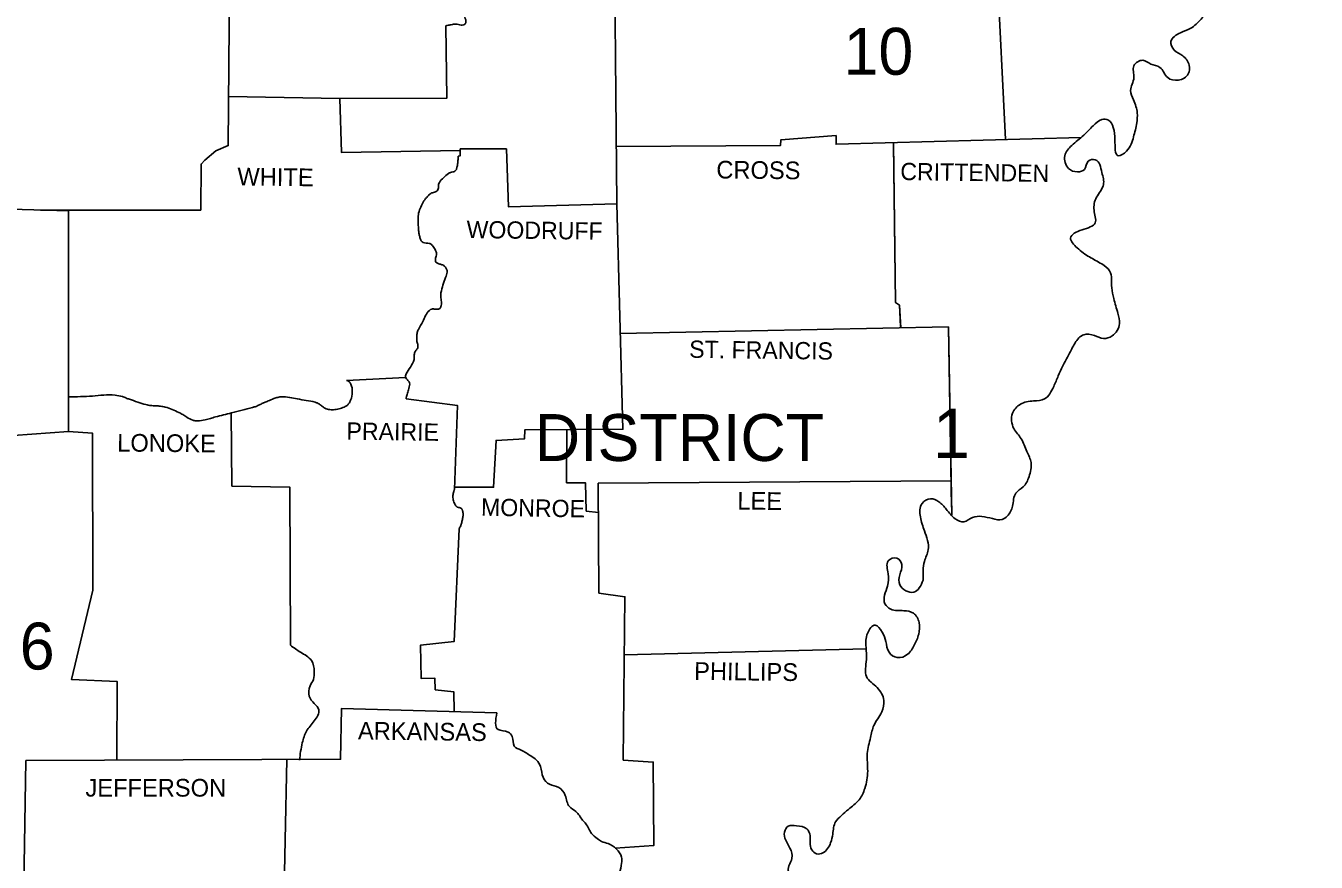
# Model space of a CAD drawing. Extents: x 164 to 3385, y 68 to 2119.
# Drawn here: x 2994.5 to 3298, y 1627.9 to 1824.7 of the extents above; entities that cross this region are included whole.
import ezdxf

# ---------------------------------------------------------------- set-up
doc = ezdxf.new("R2010")
doc.units = 0
doc.layers.add('Default', color=7, linetype='Continuous')

msp = doc.modelspace()

# ---------------------------------------------------------------- linework, layer by layer
at = {"layer": 'Default'}
msp.add_line((3096.73, 1795.77), (3107.55, 1795.77), dxfattribs=at)
for points in [[(3087.23, 1952.28), (3086.86, 1949.35), (3088.8, 1949.06), (3088.7, 1947.89), (3090.92, 1947.41), (3091.12, 1945.86), (3092.18, 1945.18), (3092.47, 1940.54), (3097.99, 1939.96), (3097.99, 1935.8), (3100.02, 1935.51), (3100.02, 1933.86), (3101.76, 1933.38), (3101.67, 1927.77), (3103.21, 1927.48), (3103.6, 1914.8), (3095.38, 1914.02), (3095.47, 1911.31), (3092.96, 1911.22), (3093.83, 1861.28), (3132.83, 1860.41), (3133.5, 1782.8), (3108.05, 1782.13), (3107.55, 1795.77)], [(2998.21, 1950.89), (2998.41, 1927.28), (2996.77, 1927.19), (2997.06, 1903.09), (2990.28, 1902.12), (2990.86, 1895.64), (2993.19, 1892.64), (2992.99, 1884.99), (2979.83, 1884.51), (2979.35, 1872.7), (2967.35, 1872.32), (2966.77, 1857.99), (2967.45, 1856.83), (2967.74, 1833.99), (2988.45, 1832.64), (2988.16, 1781.64), (3004.61, 1781.16), (3004.61, 1729.29), (2991.64, 1728.32), (2990.67, 1716.9), (2968.9, 1716.81)], [(3221.35, 1880.05), (3223.01, 1837.58), (3224.98, 1797.93)], [(2988.45, 1832.64), (3038.19, 1832.35), (3042.44, 1834.38), (3042.15, 1796.54), (3039.25, 1795.29), (3036.64, 1793.06), (3035.77, 1792.19), (3035.67, 1781.35), (2998.02, 1781.35)], [(3093.34, 1824.7), (3093.54, 1807.67), (3068.38, 1807.58), (3042.24, 1808.07)], [(3068.38, 1807.58), (3068.76, 1794.9), (3096.73, 1795.4)], [(3133.38, 1796.34), (3172.02, 1796.54), (3172.11, 1797.9), (3185.08, 1798.87), (3185.08, 1796.83), (3242.73, 1798.42)], [(3198.62, 1797.21), (3199.11, 1759.58), (3199.98, 1759), (3200.29, 1753.64)], [(3198.63, 1796.83), (3199.11, 1759.58), (3199.98, 1759), (3200.27, 1753.97)], [(3198.63, 1796.83), (3199.11, 1759.58), (3199.98, 1759), (3200.27, 1753.97)], [(3198.63, 1796.83), (3199.11, 1759.58), (3199.98, 1759), (3200.27, 1753.97)], [(3198.63, 1796.83), (3199.11, 1759.58), (3199.98, 1759), (3200.27, 1753.97)], [(3096.73, 1795.77), (3096.73, 1794.13), (3096.25, 1794.03)], [(3133.5, 1782.8), (3134.95, 1729.77), (3111.92, 1729.68), (3111.83, 1727.55), (3105.15, 1727.16), (3104.57, 1716.13), (3095.39, 1716.13)], [(3134.34, 1752.31), (3211.5, 1753.87)], [(3211.5, 1753.87), (3212.27, 1711.48)], [(3211.5, 1753.87), (3212.27, 1711.48)], [(3211.5, 1753.87), (3212.27, 1711.48)], [(3211.5, 1753.87), (3212.27, 1711.48)], [(3211.5, 1753.87), (3212.27, 1711.48)], [(3211.5, 1753.87), (3212.27, 1711.48)], [(3211.5, 1753.87), (3212.27, 1711.48)], [(3211.5, 1753.87), (3212.31, 1709.54)], [(3069.93, 1741.29), (3083.85, 1741.96)], [(3083.96, 1736.93), (3096.05, 1735.39), (3095.38, 1715.64)], [(3042.83, 1733.74), (3043.02, 1716.42), (3056.67, 1716.13), (3056.76, 1678.97)], [(3004.61, 1729.29), (3010.22, 1728.9), (3010.32, 1691.94), (3005.28, 1670.94), (3016.02, 1670.45), (3015.92, 1651.96)], [(3121.8, 1729.72), (3121.7, 1717.19), (3126.15, 1717.19), (3126.34, 1710.52), (3129.2, 1710.22)], [(3133.18, 1631.26), (3142.21, 1631.84), (3142.12, 1651.48), (3135.05, 1651.97), (3135.44, 1690.39), (3129.34, 1691.26), (3129.15, 1717.1), (3212.16, 1717.68)], [(3096.44, 1706.35), (3095.28, 1679.84), (3087.34, 1678.97), (3087.54, 1671.13), (3090.73, 1671.23), (3090.83, 1668.52), (3095.18, 1668.03), (3095.32, 1663.36)], [(3135.3, 1676.73), (3192.16, 1678.15)], [(3105.34, 1663.1), (3068.76, 1664.07), (3068.57, 1652.16), (2994.54, 1651.87)], [(2994.54, 1651.87), (2993.96, 1612.58), (2991.74, 1612.49), (2991.45, 1588.2)], [(3055.93, 1652.11), (3055.12, 1614.13), (3068.57, 1613.07)]]:
    msp.add_lwpolyline(points, dxfattribs=at)
for points in [[(3284.46, 1883.25), (3285.53, 1883.35), (3288.82, 1879.86), (3290.27, 1876.96), (3292.4, 1875.32), (3294.82, 1874.45), (3296.66, 1872.22), (3297.91, 1869.8), (3297.24, 1867.67), (3294.53, 1867.48), (3291.53, 1866.99), (3288.62, 1867.09), (3286.3, 1865.15), (3288.43, 1862.54), (3291.24, 1860.12), (3292.01, 1857.51), (3290.46, 1854.99), (3287.37, 1853.64), (3284.37, 1852.48), (3281.66, 1850.16), (3280.4, 1847.93), (3277.4, 1846.96), (3274.3, 1846.09), (3271.59, 1845.8), (3268.5, 1845.22), (3265.5, 1843.77), (3264.24, 1841.25), (3264.63, 1837.67), (3264.53, 1833.9), (3267.72, 1832.64), (3270.53, 1832.54), (3273.24, 1831.09), (3272.95, 1828.96), (3270.92, 1826.25), (3268.5, 1824.12), (3266.08, 1823.06), (3263.85, 1821.03), (3264.63, 1819), (3266.66, 1817.64), (3268.11, 1815.41), (3267.92, 1813.38), (3265.59, 1811.93), (3263.08, 1812.51), (3261.24, 1814.93), (3259.11, 1815.71), (3257.27, 1816.58), (3255.14, 1815.32), (3255.14, 1812.51), (3254.37, 1809.51), (3255.05, 1807.29), (3255.92, 1804.19), (3255.82, 1801.87), (3255.05, 1798.58), (3253.4, 1795.19), (3251.47, 1794.13), (3250.69, 1797.8), (3250.3, 1800.8), (3249.14, 1802.54), (3247.59, 1802.64), (3245.56, 1801.19), (3243.34, 1798.96), (3240.53, 1796.54), (3238.88, 1794.13), (3239.76, 1791.13), (3241.88, 1790.35), (3243.53, 1790.93), (3244.4, 1792.87), (3246.05, 1793.16), (3247.59, 1790.16)], [(3111.31, 1860.89), (3110.44, 1858.71), (3109.5, 1856.54), (3109.17, 1855.81), (3108.83, 1855.09), (3108.48, 1854.36), (3108.15, 1853.64), (3107.91, 1853.02), (3107.72, 1852.38), (3107.52, 1851.74), (3107.28, 1851.12), (3106.92, 1850.68), (3106.41, 1850.34), (3105.88, 1850.04), (3105.64, 1849.87), (3105.44, 1849.67), (3105.27, 1849.36), (3105.16, 1848.99), (3105.05, 1848.62), (3104.86, 1848.32), (3104.49, 1848.12), (3104.04, 1848.04), (3103.58, 1847.96), (3103.21, 1847.74), (3103.03, 1847.51), (3102.85, 1847.28), (3102.52, 1846.81), (3102.23, 1846.31), (3101.96, 1845.8), (3101.79, 1845.37), (3101.67, 1844.92), (3101.55, 1844.48), (3101.38, 1844.06), (3101.1, 1843.81), (3100.71, 1843.66), (3100.32, 1843.51), (3100.02, 1843.28), (3099.89, 1843.05), (3099.79, 1842.79), (3099.66, 1842.22), (3099.54, 1841.66), (3099.41, 1841.27), (3099.34, 1841.16), (3099.07, 1840.85), (3098.71, 1840.58), (3098.35, 1840.31), (3098.09, 1839.99), (3098.03, 1839.54), (3098.17, 1839.01), (3098.29, 1838.5), (3098.18, 1838.06), (3098.1, 1837.97), (3098.02, 1837.88), (3097.47, 1837.38), (3097.08, 1837.06), (3096.73, 1836.7), (3096.4, 1836.35), (3096.07, 1835.98), (3095.78, 1835.6), (3095.66, 1835.38), (3095.57, 1835.16), (3095.45, 1834.09), (3095.57, 1833.03), (3095.64, 1832.32), (3095.72, 1831.61), (3095.85, 1830.91), (3095.94, 1830.56), (3096.05, 1830.22), (3096.26, 1829.79), (3096.52, 1829.38), (3096.78, 1828.99), (3097.02, 1828.58), (3097.49, 1827.52), (3097.7, 1826.98), (3097.89, 1826.45), (3098, 1826.1), (3098.06, 1825.73), (3098.02, 1825.38), (3097.93, 1825.23), (3097.87, 1825.16), (3097.8, 1825.09), (3097.2, 1824.87), (3096.59, 1824.92), (3095.98, 1825.07), (3095.68, 1825.11), (3095.38, 1825.09), (3094.87, 1825.01), (3094.36, 1824.92), (3093.85, 1824.82), (3093.34, 1824.7)], [(3096.25, 1794.03), (3096.19, 1793.22), (3096.11, 1792.42), (3095.99, 1791.62), (3095.89, 1791.23), (3095.83, 1791.03), (3095.76, 1790.83), (3095.45, 1790.48), (3094.95, 1790.31), (3094.4, 1790.18), (3094.15, 1790.09), (3093.92, 1789.96), (3092.79, 1788.97), (3091.8, 1787.84), (3091.61, 1787.38), (3091.57, 1786.85), (3091.52, 1786.33), (3091.31, 1785.9), (3091.14, 1785.75), (3090.93, 1785.64), (3090.45, 1785.5), (3089.97, 1785.37), (3089.57, 1785.13), (3089.11, 1784.66), (3088.68, 1784.18), (3088.28, 1783.66), (3087.92, 1783.09), (3087.26, 1781.72), (3086.86, 1780.29), (3086.78, 1778.84), (3086.86, 1777.38), (3086.93, 1776.55), (3087.04, 1775.72), (3087.23, 1774.9), (3087.37, 1774.5), (3087.54, 1774.09), (3087.99, 1773.7), (3088.66, 1773.6), (3089.38, 1773.52), (3089.96, 1773.22), (3090.15, 1773), (3090.33, 1772.78), (3090.64, 1772.3), (3091.12, 1771.29), (3091.14, 1770.79), (3091, 1770.26), (3090.87, 1769.74), (3090.92, 1769.25), (3091.38, 1768.83), (3092.05, 1768.6), (3092.74, 1768.36), (3093.25, 1767.9), (3093.41, 1767.61), (3093.56, 1767.32), (3093.65, 1767.03), (3093.63, 1766.74), (3093.25, 1765.48), (3092.18, 1761.9), (3092.11, 1761.31), (3092.16, 1760.7), (3092.24, 1760.09), (3092.28, 1759.48), (3092.24, 1758.94), (3092.18, 1758.68), (3092.09, 1758.42), (3091.58, 1758.05), (3090.81, 1758.04), (3090.02, 1758.05), (3089.47, 1757.74), (3087.92, 1755.13), (3086.86, 1753.29), (3086.73, 1752.99), (3086.53, 1752.08), (3086.49, 1751.48), (3086.47, 1750.87), (3086.52, 1750.43), (3086.64, 1750), (3086.75, 1749.56), (3086.76, 1749.13), (3086.63, 1748.77), (3086.4, 1748.44), (3086.16, 1748.12), (3085.99, 1747.77), (3085.91, 1747.27), (3085.9, 1746.74), (3085.85, 1746.22), (3085.7, 1745.74), (3084.73, 1744), (3083.86, 1742.35), (3083.89, 1741.88), (3084.27, 1741.4), (3084.68, 1740.91), (3084.83, 1740.42), (3084.69, 1739.75), (3084.54, 1739.06), (3084.39, 1738.53), (3084.22, 1737.99), (3083.96, 1736.93)], [(3247.59, 1790.16), (3247.98, 1787.35), (3246.34, 1784.35), (3245.76, 1781.35), (3246.05, 1778.35), (3242.95, 1776.71), (3240.24, 1774.77), (3241.79, 1772.45), (3244.69, 1770.32), (3247.59, 1768.67), (3249.43, 1767.03), (3249.92, 1763.06), (3250.4, 1760.55), (3251.37, 1757.06), (3251.76, 1754.64), (3250.01, 1751.74), (3247.98, 1751.16), (3245.85, 1751.84), (3243.34, 1752.03), (3241.3, 1750.09), (3239.85, 1747.38), (3238.4, 1744.68), (3237.34, 1742.35), (3236.27, 1739.84), (3234.14, 1736.93), (3231.53, 1736.45), (3228.43, 1735.68), (3226.6, 1733.55), (3226.89, 1729.97), (3228.63, 1727.55), (3229.98, 1724.55), (3230.95, 1721.93), (3230.47, 1718.64), (3229.11, 1716.22), (3227.37, 1714.77), (3226.6, 1711.68), (3225.34, 1709.35), (3224.18, 1708.58), (3221.85, 1708.77), (3219.34, 1709.26), (3217.21, 1709.06), (3215.18, 1708), (3213.14, 1708.68), (3211.02, 1711), (3209.27, 1712.74), (3207.34, 1713.42), (3205.31, 1712.35), (3204.92, 1709.16), (3205.89, 1705.87), (3206.76, 1701.42), (3205.89, 1698.71), (3205.6, 1694.26)], [(3004.61, 1737.41), (3010.22, 1737.61), (3015.54, 1737.8), (3017.25, 1737.46), (3018.09, 1737.14), (3018.51, 1736.98), (3018.93, 1736.84), (3022.8, 1735.58), (3023.35, 1735.45), (3023.92, 1735.37), (3025.07, 1735.29), (3026.22, 1735.21), (3027.35, 1735), (3030.54, 1733.74), (3031.02, 1733.5), (3031.48, 1733.22), (3032.4, 1732.62), (3033.82, 1731.91), (3034.06, 1731.84), (3034.31, 1731.8), (3034.91, 1731.78), (3036.73, 1732.02), (3037.95, 1732.34), (3039.15, 1732.68), (3042.93, 1733.64), (3047.86, 1734.9), (3048.68, 1735.17), (3049.47, 1735.53), (3050.26, 1735.91), (3051.06, 1736.26), (3051.51, 1736.44), (3052.87, 1737), (3053.79, 1737.29), (3054.26, 1737.38), (3054.73, 1737.42), (3056.57, 1737.26), (3058.41, 1736.93), (3060.5, 1736.57), (3062.57, 1736.16), (3063.27, 1735.88), (3063.92, 1735.43), (3064.54, 1734.96), (3065.18, 1734.61), (3066.32, 1734.38), (3067.55, 1734.45), (3068.79, 1734.77), (3069.38, 1735.01), (3069.93, 1735.29), (3070.51, 1735.83), (3070.94, 1736.62), (3071.33, 1738.57), (3071.01, 1740.39), (3070.57, 1741), (3069.93, 1741.29)], [(3095.38, 1715.64), (3095.26, 1715.41), (3095.17, 1715.17), (3095.05, 1714.68), (3094.99, 1714.19), (3094.98, 1713.95), (3094.99, 1713.71), (3095.06, 1713.19), (3095.23, 1712.67), (3095.47, 1712.17), (3095.61, 1711.92), (3095.76, 1711.68), (3095.9, 1711.54), (3096.07, 1711.45), (3096.47, 1711.35), (3096.86, 1711.25), (3097.01, 1711.15), (3097.07, 1711.08), (3097.12, 1711), (3097.16, 1710.88), (3097.21, 1710.76), (3097.36, 1710.03), (3097.37, 1709.54), (3097.35, 1709.3), (3097.31, 1709.06), (3097.12, 1708.09), (3096.99, 1707.61), (3096.92, 1707.37), (3096.83, 1707.13), (3096.65, 1706.73), (3096.44, 1706.35)], [(3205.6, 1694.26), (3203.37, 1691.45), (3200.08, 1693.19), (3200.08, 1695.52), (3200.56, 1697.93), (3199.4, 1699.48), (3197.37, 1698.81), (3197.37, 1695.81), (3197.18, 1692.9), (3196.6, 1688.74), (3197.95, 1687.48), (3201.05, 1687.1), (3203.27, 1686.52), (3204.63, 1684.29), (3204.53, 1681.58), (3203.47, 1678.97), (3201.92, 1676.84), (3199.5, 1676.06), (3197.56, 1677.32), (3196.79, 1679.84), (3195.92, 1682.06), (3194.27, 1683.71), (3192.53, 1681.87), (3192.15, 1678.48), (3192.24, 1675.58), (3192.24, 1671.61), (3194.76, 1669), (3196.31, 1666), (3195.82, 1663.29), (3193.98, 1660.1), (3193.21, 1657.29), (3192.44, 1653.52), (3192.53, 1649.36), (3191.86, 1645.29), (3190.5, 1642.58), (3187.98, 1640.36), (3186.34, 1638.9), (3184.98, 1637.45), (3184.31, 1634.55), (3183.82, 1632.52), (3181.98, 1630.1), (3180.53, 1629.9), (3179.37, 1630.87), (3178.98, 1632.52), (3178.98, 1634.16), (3178.21, 1635.81), (3175.79, 1636.49), (3173.86, 1636.39), (3172.98, 1635.03), (3174.24, 1631.26), (3174.73, 1628.84), (3174.05, 1625.55), (3174.44, 1625.16), (3170.95, 1623.32), (3168.15, 1623.03), (3165.82, 1622.36), (3163.6, 1620.91), (3162.53, 1618.78), (3160.99, 1617.03), (3159.63, 1615.39), (3157.79, 1614.62), (3155.76, 1615), (3153.05, 1615.29), (3151.5, 1613.36), (3151.99, 1610.55), (3153.82, 1608.91), (3156.53, 1608.13), (3159.34, 1608.33), (3162.05, 1608.62), (3164.57, 1607.26), (3164.08, 1604.65), (3161.66, 1603.39), (3158.08, 1603), (3155.18, 1603.29), (3151.7, 1602.52), (3149.95, 1600.29), (3150.92, 1596.91), (3154.7, 1595.55), (3156.44, 1592.36), (3156.53, 1589.36), (3155.28, 1585.39), (3153.53, 1583.55), (3150.15, 1582.78), (3147.53, 1582.29), (3147.15, 1577.84), (3145.99, 1575.62), (3143.95, 1574.94), (3141.05, 1576.39), (3139.31, 1577.07), (3137.18, 1578.04), (3134.47, 1579.68), (3132.44, 1579.39), (3133.02, 1575.13), (3133.21, 1574.94), (3135.54, 1571.75), (3137.86, 1569.23), (3138.92, 1566.23)], [(3056.76, 1678.97), (3059.18, 1677.32), (3061.7, 1675.39), (3062.38, 1672.77), (3062.18, 1670.94), (3061.41, 1669.39), (3061.22, 1666.97), (3062.38, 1665.23), (3063.44, 1663.77), (3062.38, 1661.16), (3060.54, 1658.74), (3059.57, 1656.03), (3058.89, 1651.97)], [(3105.34, 1663.1), (3105.63, 1659.13), (3107.96, 1658.55), (3108.92, 1657.48), (3109.41, 1655.26), (3111.05, 1654.29), (3113.28, 1652.94), (3114.63, 1651.97), (3115.6, 1650.42), (3116.18, 1647.9), (3117.73, 1646.26), (3119.86, 1645.49), (3121.41, 1643.65), (3122.37, 1641.03), (3123.92, 1639.87), (3125.47, 1637.84), (3126.25, 1636.97), (3127.6, 1634.65), (3128.95, 1633.49), (3129.92, 1632.81), (3131.47, 1632.32), (3133.41, 1631.07), (3134.66, 1629.13), (3134.66, 1627.68), (3134.18, 1625.45), (3133.79, 1623.13), (3133.6, 1620.52), (3133.41, 1618.2), (3134.28, 1616.26), (3133.79, 1613.36), (3132.83, 1611.81), (3132.73, 1609.68), (3132.44, 1606.49), (3132.05, 1604.65), (3131.18, 1601.65), (3129.92, 1600.1)]]:
    msp.add_spline(points, degree=3, dxfattribs=at)

# ---------------------------------------------------------------- texts
for s, height, p in [('10', 11.032, (3186.85, 1813.19)), ('DISTRICT', 11.032, (3114.25, 1722.32)), ('1', 11.61, (3207.92, 1723)), ('DISTRICT 6', 11.032, (2921, 1673.26)), ('JEFFERSON', 4.161, (3008.57, 1643.36))]:
    msp.add_text(s, height=height, dxfattribs=at).set_placement(p)
for s, height, rotation, p in [('WHITE', 4.162, 359.3138, (3044.28, 1787.16)), ('CROSS', 4.161, 359.3839, (3156.92, 1788.8)), ('CRITTENDEN', 4.065, 359.213, (3200.18, 1788.42)), ('WOODRUFF', 4.064, 359.2748, (3098.18, 1774.77)), ('ST. FRANCIS', 4.0637, 359.2216, (3150.53, 1746.61)), ('PRAIRIE', 4.065, 359.2116, (3069.93, 1727.35)), ('LONOKE', 4.162, 359.4974, (3016.02, 1724.55)), ('LEE', 4.162, 359.4327, (3161.86, 1710.9)), ('MONROE', 4.064, 359.0331, (3101.57, 1709.45)), ('PHILLIPS', 4.161, 359.3179, (3151.7, 1670.84)), ('ARKANSAS', 4.161, 359.2678, (3072.63, 1656.81))]:
    msp.add_text(s, height=height, rotation=rotation, dxfattribs=at).set_placement(p)

doc.saveas('drawing.dxf')
